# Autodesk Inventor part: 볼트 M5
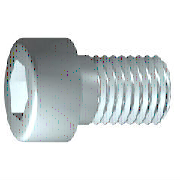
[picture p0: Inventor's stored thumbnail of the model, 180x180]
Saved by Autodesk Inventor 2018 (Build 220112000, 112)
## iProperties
IsCustomPart: 1
Created: 2012-02
Part Number: 볼트 M5
Material: 강철, 연강
Description: 6각머리 태핑 나사
Document SubType Name: Modeling
Standard: KS B 1003
Designer: mduedu
Standards Organization: KS
Language: ko-KR
Size Designation: M 5 x 12
Categories: <MemberInstance><Categories><Category DisplayName="조임쇠" InternalName="e4da775c-781d-43d5-af7c-5136215cf5a6" Mnemonic="FSTN"><Category DisplayName="볼트" InternalN
Density: 1 g/cm^3
Appearance: 강철
Author: mduedu
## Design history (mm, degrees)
sketch "스케치1"
  geometry: L1 (-1.167, 0)-(12, 0); L2 (12, 0)-(12, 2.5); L3 (12, 2.5)-(2, 2.5); L4 (2, 2.5)-(1.509, 2.5); L5 (1.509, 2.5)-(0, 2.5); L6 (0, 2.5)-(0, 4.25); L7 (0, 4.25)-(-5, 4.25); L8 (-5, 4.25)-(-5, 2.309); L9 (-5, 2.309)-(-2.5, 2.309); L10 (-2.5, 2.309)-(-1.167, 0); L11 (-8.4, 0)-(15.4, 0) reference; L12 (0, -0.85)-(0, 5.1) reference; L13 (2, 2.5)-(0, 2.5)
  constraints: 22 end point, 6 parallel, 2 collinear, 2 perpendicular, 1 horizontal, 1 point on line
  dimensions: "d1" = 10 distance from line of L3.end L2 (= GEL); "d2" = 0.49086 distance of L4.end L3.end (computed from GAL); "d3" = 5 distance between parallel lines of L8 L6 (= KOH); "d4" = 2.5 distance of L8.end L9.end (= INTI); "d5" = 60 deg angle of L10 L1; "d6" = 5 diameter of L3 L1 (= GD); "d7" = 5 diameter of L5 L1 (= BDM); "d8" = 4.6188 diameter of L9 L1 (= 1.1547 x SW); "d9" = 8.5 diameter of L7 L1 (= KOD); "d26" = 12 distance between parallel lines of L12 L2 (= NLG)
revolve "본체" sketch "스케치1" stored, may be unused: angle "d10" = 90 deg
sketch "스케치2"
  geometry: L1 (0, -5.95)-(0, 5.95) reference; L2 (-5.95, 0)-(5.95, 0) reference; L3 (2.309, 0)-(1.155, -2); L4 (1.155, -2)-(-1.155, -2); L5 (-1.155, -2)-(-2.309, 0); L6 (-2.309, 0)-(-1.155, 2); L7 (-1.155, 2)-(1.155, 2); L8 (1.155, 2)-(2.309, 0); 2 further points
  constraints: 12 end point, 1 coincident, 1 horizontal alignment, 1 point on line, 12 other
extrude "슬롯" join sketch "스케치2" stored distance "d11" = 10; taper "d12" = 0 deg
workplane "Work Plane1"
fillet "Fillet2" dims "d30" = 0.1 (= R)
body "Solid1"
fillet "모깎기1" dims "d17" = 0.5 (= RR)
feature "스레드" dims "d13" = 10 (= GEL), "d14" = 0
chamfer "모따기1" distance "d15" = 0.49076 (= -0.5 x SPD + 0.5 x GD); stored, may be unused: second distance "d16" = 0.49076 (= GUL), angle "d27" = 45 deg
other parameters: "GD" = 5 (= NND) [user parameter; used in 2 equation terms], "NLG" = 12 [user parameter; used in 1 equation term], "GEL" = 10 [user parameter; used in 2 equation terms], "KOD" = 8.5 [user parameter; used in 1 equation term], "KOH" = 5 [user parameter; used in 1 equation term], "INTI" = 2.5 [user parameter; used in 1 equation term], "GAL" = 0.49076 (= 0.61345 x PTC) [user parameter; used in 1 equation term], "GUL" = 0.49076 (= 0.61345 x PTC) [user parameter; used in 1 equation term], "BDM" = 5 (= NND) [user parameter; used in 1 equation term], "SW" = 4 [user parameter; used in 2 equation terms], "RR" = 0.5 [user parameter; used in 1 equation term], "SPD" = 4.01848 (= NND - 1.2269 x PTC) [user parameter; used in 1 equation term], "d19" = 0, "d28" = 0, "d29" = 0, "R" = 0.1 [user parameter; used in 1 equation term], "PHH" = 0.2 [user parameter], "GD1" = 4.01848 (= THREADDIA - 1.2269 x PTC) [user parameter], "THREADDIA" = 5 [user parameter; used in 1 equation term], "FAWI" = 45 deg [user parameter], "TPU" = 12.5 (computed from PTC) [user parameter], "PTC" = 0.8 [user parameter; used in 5 equation terms], "NND" = 5 [user parameter; used in 3 equation terms], "TOA" = 30 deg [user parameter], "E0" = 4.62 (= 1.155 x SW) [user parameter]
